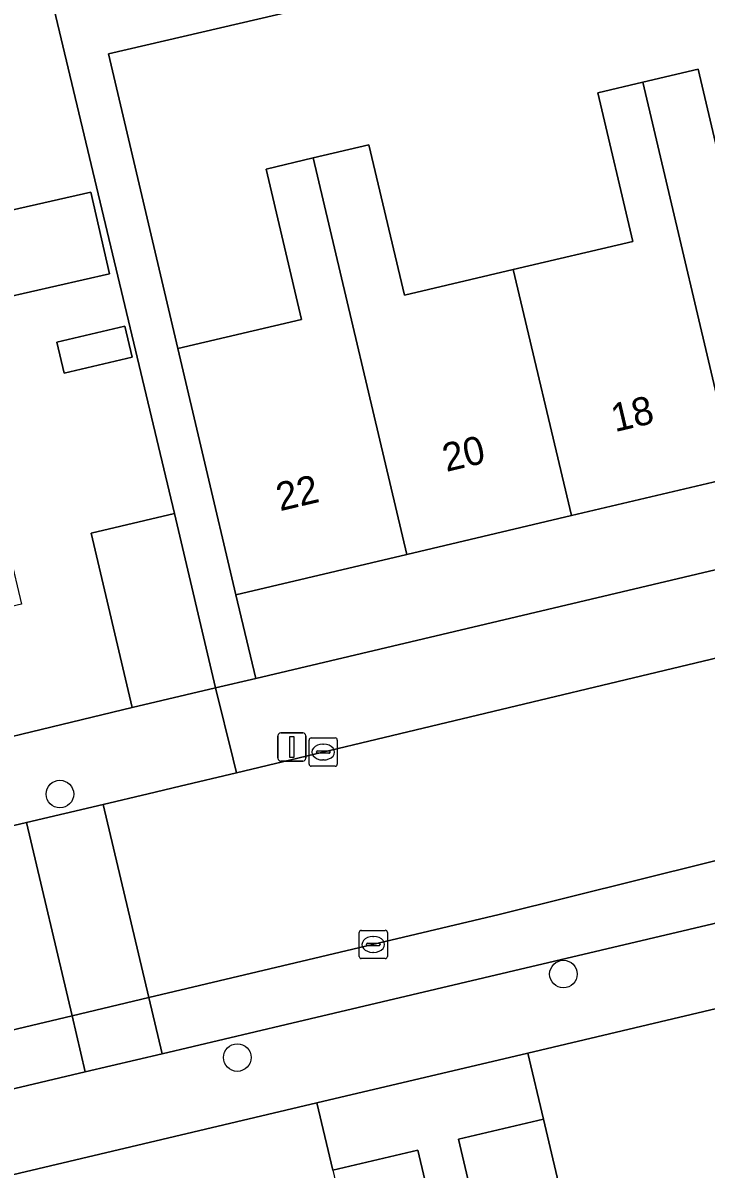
# Model space of a CAD drawing. Extents: x 158031 to 159244, y 380104 to 381214.
# Drawn here: x 158544.18 to 158568.41, y 380857.98 to 380898.59 of the extents above; entities that cross this region are included whole.
import ezdxf

# ---------------------------------------------------------------- set-up
doc = ezdxf.new("R2010")
doc.units = 0
for name, color, linetype in [('IMGEO_Boom', 7, 'Continuous'), ('IMGEO_Erf', 7, 'Continuous'), ('IMGEO_Kolk', 7, 'Continuous'), ('IMGEO_Lichtmast', 7, 'Continuous'), ('IMGEO_Muur', 7, 'Continuous'), ('IMGEO_Pand', 7, 'Continuous'), ('IMGEO_Pand_nummerreeks', 7, 'Continuous'), ('IMGEO_Parkeervlak_open', 7, 'Continuous'), ('IMGEO_Rijbaan_lokaal_open', 7, 'Continuous'), ('IMGEO_Voetpad_open', 7, 'Continuous')]:
    doc.layers.add(name, color=color, linetype=linetype)

msp = doc.modelspace()

# ---------------------------------------------------------------- linework, layer by layer
at = {"layer": 'IMGEO_Boom'}
for centre in [(158545.492, 380871.264), (158563.349, 380864.886), (158551.783, 380861.928)]:
    msp.add_circle(centre, 0.489, dxfattribs=at)
at = {"layer": 'IMGEO_Erf'}
for points in [[(158606.012, 380911.202), (158556.488, 380899.652), (158547.216, 380897.489), (158549.679, 380887.047), (158554.058, 380888.08), (158552.802, 380893.406), (158554.479, 380893.802), (158556.452, 380894.267), (158557.71, 380888.938), (158561.571, 380889.849), (158565.808, 380890.848), (158564.567, 380896.11), (158566.165, 380896.487), (158568.13, 380896.951), (158569.362, 380891.729)], [(158533.265, 380899.992), (158534.208, 380895.991), (158535.134, 380892.064), (158540.475, 380893.323), (158540.95, 380891.312), (158546.587, 380892.596), (158547.246, 380889.7), (158541.633, 380888.421), (158541.336, 380889.674), (158536.03, 380888.423), (158536.992, 380884.344), (158537.924, 380880.39), (158541.206, 380881.164), (158541.674, 380879.254), (158543.722, 380879.737), (158544.132, 380877.998), (158542.099, 380877.519), (158540.201, 380877.071), (158538.788, 380876.738), (158539.823, 380872.349), (158548.06, 380874.33), (158546.602, 380880.51), (158549.557, 380881.207), (158542.574, 380910.402)], [(158569.467, 380882.508), (158563.63, 380881.131), (158557.795, 380879.754), (158551.737, 380878.325), (158552.436, 380875.363), (158619.145, 380891.13)], [(158569.224, 380863.769), (158562.085, 380862.085), (158562.638, 380859.742), (158564.08, 380853.629), (158561.065, 380852.917), (158567.641, 380824.075), (158568.7, 380824.316)], [(158555.166, 380857.934), (158554.603, 380860.32), (158535.255, 380855.756)]]:
    msp.add_lwpolyline(points, dxfattribs=at)
msp.add_lwpolyline([(158545.384, 380887.277), (158547.789, 380887.845), (158548.049, 380886.744), (158545.644, 380886.176)], close=True, dxfattribs=at)
at = {"layer": 'IMGEO_Kolk'}
for p, q in [((158554.328, 380872.326), (158554.328, 380873.178)), ((158554.403, 380873.252), (158555.255, 380873.252)), ((158554.816, 380873.032), (158554.841, 380873.032)), ((158555.329, 380873.178), (158555.329, 380872.326)), ((158554.587, 380872.746), (158554.587, 380872.758)), ((158555.025, 380872.709), (158554.627, 380872.709)), ((158554.63, 380872.795), (158555.028, 380872.795)), ((158555.071, 380872.758), (158555.071, 380872.746)), ((158555.255, 380872.252), (158554.403, 380872.252)), ((158554.839, 380872.472), (158554.814, 380872.472)), ((158556.104, 380865.509), (158556.104, 380866.361)), ((158556.179, 380866.435), (158557.031, 380866.435)), ((158556.592, 380866.215), (158556.617, 380866.215)), ((158557.105, 380866.361), (158557.105, 380865.509)), ((158556.363, 380865.929), (158556.363, 380865.941)), ((158556.801, 380865.892), (158556.403, 380865.892)), ((158556.406, 380865.978), (158556.804, 380865.978)), ((158556.847, 380865.941), (158556.847, 380865.929)), ((158557.031, 380865.435), (158556.179, 380865.435)), ((158556.615, 380865.655), (158556.59, 380865.655))]:
    msp.add_line(p, q, dxfattribs=at)
for points in [[(158554.328, 380872.326), (158554.328, 380873.178)], [(158554.403, 380873.252), (158555.255, 380873.252)], [(158555.329, 380873.178), (158555.329, 380872.326)], [(158555.255, 380872.252), (158554.403, 380872.252)], [(158556.104, 380865.509), (158556.104, 380866.361)], [(158556.179, 380866.435), (158557.031, 380866.435)], [(158557.105, 380866.361), (158557.105, 380865.509)], [(158557.031, 380865.435), (158556.179, 380865.435)]]:
    msp.add_lwpolyline(points, dxfattribs=at)
for centre, radius, start, end in [((158554.405, 380873.176), 0.0765, 91.552, 178.448), ((158554.405, 380873.176), 0.0765, 91.552, 178.448), ((158555.253, 380873.176), 0.0765, 1.552, 88.448), ((158555.253, 380873.176), 0.0765, 1.552, 88.448), ((158554.627, 380872.755), 0.0403, 85.8775, 175.7526), ((158554.624, 380872.745), 0.0366, 178.938, 274.7102), ((158555.028, 380872.752), 0.043, 264.8664, 352.4533), ((158555.032, 380872.757), 0.0386, 1.7309, 96.639), ((158554.405, 380872.328), 0.0765, 181.552, 268.448), ((158554.405, 380872.328), 0.0765, 181.552, 268.448), ((158555.253, 380872.328), 0.0765, 271.552, 358.448), ((158555.253, 380872.328), 0.0765, 271.552, 358.448), ((158556.181, 380866.359), 0.0765, 91.552, 178.448), ((158556.181, 380866.359), 0.0765, 91.552, 178.448), ((158557.029, 380866.359), 0.0765, 1.552, 88.448), ((158557.029, 380866.359), 0.0765, 1.552, 88.448), ((158556.403, 380865.938), 0.0403, 85.8775, 175.7526), ((158556.4, 380865.928), 0.0366, 178.938, 274.7102), ((158556.804, 380865.935), 0.043, 264.8664, 352.4533), ((158556.808, 380865.94), 0.0386, 1.7309, 96.639), ((158556.181, 380865.511), 0.0765, 181.552, 268.448), ((158556.181, 380865.511), 0.0765, 181.552, 268.448), ((158557.029, 380865.511), 0.0765, 271.552, 358.448), ((158557.029, 380865.511), 0.0765, 271.552, 358.448)]:
    msp.add_arc(centre, radius, start, end, dxfattribs=at)
for centre, major_axis, ratio, start_param, end_param in [((158554.815, 380872.752), (-0.387, 0.002), 0.722429, 4.712389, 7.853982), ((158554.84, 380872.752), (-0.39, 0.002), 0.717154, 1.570796, 4.712389), ((158556.591, 380865.935), (-0.387, 0.002), 0.722429, 4.712389, 7.853982), ((158556.616, 380865.935), (-0.39, 0.002), 0.717154, 1.570796, 4.712389)]:
    msp.add_ellipse(centre, major_axis=major_axis, ratio=ratio, start_param=start_param, end_param=end_param, dxfattribs=at)
at = {"layer": 'IMGEO_Lichtmast'}
for p, q in [((158553.322, 380873.431), (158554.112, 380873.431)), ((158554.112, 380873.431), (158553.322, 380873.431)), ((158553.222, 380872.531), (158553.222, 380873.331)), ((158553.222, 380873.331), (158553.222, 380872.531)), ((158554.212, 380873.331), (158554.212, 380872.531)), ((158554.212, 380872.531), (158554.212, 380873.331)), ((158554.112, 380872.431), (158553.322, 380872.431)), ((158553.322, 380872.431), (158554.112, 380872.431))]:
    msp.add_line(p, q, dxfattribs=at)
msp.add_lwpolyline([(158553.642, 380873.306), (158553.792, 380873.306), (158553.792, 380872.556), (158553.642, 380872.556), (158553.642, 380873.306)], dxfattribs=at)
for centre, start, end in [((158553.322, 380873.331), 90, 180), ((158553.322, 380873.331), 90, 180), ((158554.112, 380873.331), 0, 90), ((158554.112, 380873.331), 360, 90), ((158553.322, 380872.531), 180, 270), ((158553.322, 380872.531), 180, 270), ((158554.112, 380872.531), 270, 0), ((158554.112, 380872.531), 270, 0)]:
    msp.add_arc(centre, 0.1, start, end, dxfattribs=at)
at = {"layer": 'IMGEO_Muur'}
for points in [[(158539.823, 380872.349), (158548.06, 380874.33)], [(158562.085, 380862.085), (158569.224, 380863.769)]]:
    msp.add_lwpolyline(points, dxfattribs=at)
at = {"layer": 'IMGEO_Pand'}
for points in [[(158573.234, 380892.643), (158569.362, 380891.729), (158568.13, 380896.951), (158566.165, 380896.487), (158569.467, 380882.508), (158575.293, 380883.883)], [(158569.467, 380882.508), (158566.165, 380896.487), (158564.567, 380896.11), (158565.808, 380890.848), (158561.571, 380889.849), (158563.63, 380881.131)], [(158554.479, 380893.802), (158557.795, 380879.754), (158563.63, 380881.131), (158561.571, 380889.849), (158557.71, 380888.938), (158556.452, 380894.267)], [(158554.479, 380893.802), (158552.802, 380893.406), (158554.058, 380888.08), (158549.679, 380887.047), (158550.589, 380883.192), (158551.737, 380878.325), (158557.795, 380879.754)], [(158540.95, 380891.312), (158541.336, 380889.674), (158541.633, 380888.421), (158547.246, 380889.7), (158546.587, 380892.596)], [(158545.384, 380887.277), (158545.644, 380886.176), (158548.049, 380886.744), (158547.789, 380887.845)], [(158548.06, 380874.33), (158551.015, 380875.027), (158549.557, 380881.207), (158546.602, 380880.51)], [(158561.065, 380852.917), (158564.08, 380853.629), (158562.638, 380859.742), (158559.623, 380859.031)], [(158556.605, 380851.833), (158559.622, 380852.545), (158558.183, 380858.646), (158555.166, 380857.934)]]:
    msp.add_lwpolyline(points, close=True, dxfattribs=at)
at = {"layer": 'IMGEO_Parkeervlak_open'}
for points in [[(158575.942, 380870.696), (158561.071, 380866.994), (158548.646, 380864.05), (158549.117, 380862.059), (158553.511, 380863.095), (158561.381, 380864.951), (158572.759, 380867.634), (158572.944, 380867.702), (158573.122, 380867.786), (158573.291, 380867.885), (158573.451, 380867.999), (158573.601, 380868.127), (158573.738, 380868.268), (158573.862, 380868.421), (158573.935, 380868.525), (158574.629, 380869.458)], [(158546.392, 380861.417), (158549.117, 380862.059), (158548.646, 380864.05), (158545.922, 380863.405)], [(158534.08, 380860.599), (158534.608, 380858.638), (158546.392, 380861.417), (158545.922, 380863.405)]]:
    msp.add_lwpolyline(points, close=True, dxfattribs=at)
at = {"layer": 'IMGEO_Rijbaan_lokaal_open'}
msp.add_lwpolyline([(158575.76, 380877.756), (158551.754, 380872.016), (158549.756, 380871.538), (158548.628, 380871.272), (158547.027, 380870.894), (158548.646, 380864.05), (158561.071, 380866.994), (158575.942, 380870.696)], dxfattribs=at)
for points in [[(158544.303, 380870.251), (158545.922, 380863.405), (158548.646, 380864.05), (158547.027, 380870.894)], [(158472.473, 380846.056), (158500, 380852.548), (158515.207, 380856.135), (158522.175, 380857.778), (158534.08, 380860.599), (158545.922, 380863.405), (158544.303, 380870.251), (158526.184, 380865.973), (158519.469, 380864.387), (158501.877, 380860.234), (158500, 380859.786), (158470.875, 380852.834)]]:
    msp.add_lwpolyline(points, close=True, dxfattribs=at)
at = {"layer": 'IMGEO_Voetpad_open'}
for points in [[(158581.798, 380907.083), (158564.442, 380903.037), (158564.465, 380902.939), (158558.626, 380901.553), (158558.597, 380901.675), (158546.898, 380898.948), (158544.622, 380908.541), (158543.716, 380912.36), (158542.764, 380916.371), (158541.25, 380916.018), (158542.574, 380910.402), (158549.557, 380881.207), (158551.015, 380875.027), (158552.436, 380875.363), (158551.737, 380878.325), (158550.589, 380883.192), (158549.679, 380887.047), (158547.216, 380897.489), (158556.488, 380899.652), (158606.012, 380911.202)], [(158617.961, 380884.242), (158618.212, 380883.713), (158617.324, 380887.48), (158619.862, 380888.097), (158619.145, 380891.13), (158552.436, 380875.363), (158551.015, 380875.027), (158551.634, 380872.501), (158551.754, 380872.016), (158575.76, 380877.756), (158592.127, 380881.349), (158613.244, 380886.487)], [(158519.469, 380864.387), (158526.184, 380865.973), (158544.303, 380870.251), (158547.027, 380870.894), (158548.628, 380871.272), (158549.756, 380871.538), (158551.754, 380872.016), (158551.634, 380872.501), (158551.015, 380875.027), (158548.06, 380874.33), (158539.823, 380872.349), (158531.08, 380870.288), (158528.134, 380869.517), (158525.106, 380868.818), (158519.402, 380867.476), (158514.58, 380866.28), (158512.303, 380865.698), (158500, 380862.796), (158459.414, 380853.223)], [(158572.759, 380867.634), (158561.381, 380864.951), (158553.511, 380863.095), (158549.117, 380862.059), (158546.392, 380861.417), (158534.608, 380858.638), (158534.08, 380860.599), (158522.175, 380857.778), (158515.207, 380856.135), (158515.654, 380854.159), (158500, 380850.436), (158472.957, 380844.003), (158470.273, 380843.365), (158438.55, 380835.819)], [(158554.603, 380860.32), (158562.085, 380862.085), (158569.224, 380863.769)], [(158382.15, 380819.43), (158403.689, 380824.581), (158405.227, 380824.949), (158428.782, 380830.582), (158431.67, 380831.273), (158431.507, 380831.934), (158492.147, 380846.362), (158492.306, 380845.603), (158500, 380847.433), (158527.386, 380853.947), (158531.949, 380855.031), (158535.255, 380855.756), (158554.603, 380860.32)]]:
    msp.add_lwpolyline(points, dxfattribs=at)
msp.add_lwpolyline([(158575.794, 380789.538), (158577.028, 380789.836), (158568.7, 380824.316), (158567.641, 380824.075), (158561.065, 380852.917), (158559.623, 380859.031), (158562.638, 380859.742), (158562.085, 380862.085), (158554.603, 380860.32), (158555.166, 380857.934), (158558.183, 380858.646), (158559.622, 380852.545), (158566.537, 380823.228), (158556.446, 380820.79), (158552.507, 380819.856), (158547.641, 380818.703), (158544.228, 380817.894), (158544.566, 380816.468), (158549.386, 380817.61), (158554.252, 380818.763), (158558.068, 380819.667), (158568.094, 380822.042)], close=True, dxfattribs=at)

# ---------------------------------------------------------------- texts
at = {"layer": 'IMGEO_Pand_nummerreeks'}
for s, p in [('18', (158565.174, 380884.085)), ('20', (158559.193, 380882.675)), ('22', (158553.297, 380881.283))]:
    msp.add_text(s, height=1, rotation=13.2753, dxfattribs=at).set_placement(p)

doc.saveas('drawing.dxf')
